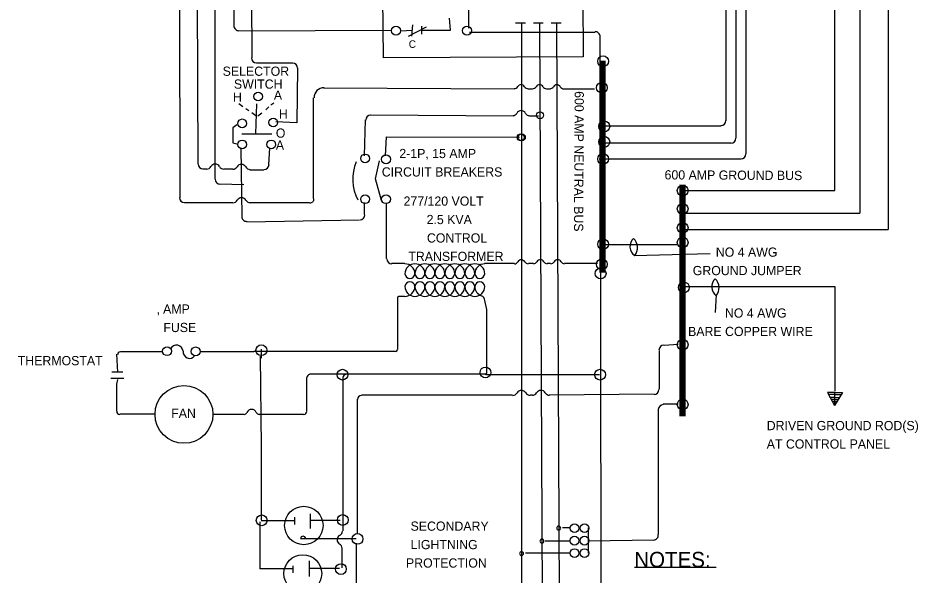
# Model space of a CAD drawing. Extents: x 10006.6 to 10036.5, y 10000 to 10010.3.
# Drawn here: x 10029.2 to 10035.06, y 10003.49 to 10007.12 of the extents above; entities that cross this region are included whole.
import ezdxf

# ---------------------------------------------------------------- set-up
doc = ezdxf.new("R2010")
doc.units = 0
for name, color, linetype in [('DETL-LINE', 7, 'Continuous'), ('DETL-NOTE', 7, 'Continuous'), ('TTLB-TEXT', 7, 'Continuous')]:
    doc.layers.add(name, color=color, linetype=linetype)

# ---------------------------------------------------------------- blocks, each defined once
blk = doc.blocks.new('CIR1')
at = {"layer": 'DETL-LINE'}
blk.add_circle((0, 0), 0.0589, dxfattribs=at)

msp = doc.modelspace()

# ---------------------------------------------------------------- linework, layer by layer
at = {"layer": 'DETL-LINE'}
for p, q in [((10030.357, 10009.214), (10030.37, 10006.172)), ((10030.715, 10009.208), (10030.721, 10006.861)), ((10030.247, 10008.844), (10030.253, 10005.951)), ((10033.809, 10006.452), (10033.809, 10008.766)), ((10033.874, 10006.341), (10033.874, 10008.766)), ((10033.939, 10006.237), (10033.939, 10008.694)), ((10034.517, 10005.9973), (10034.517, 10008.701)), ((10030.481, 10008.642), (10030.481, 10006.075)), ((10030.604, 10008.239), (10030.604, 10007.069)), ((10031.579, 10006.861), (10031.573, 10007.505)), ((10032.873, 10007.505), (10032.879, 10006.868)), ((10032.132, 10007.193), (10032.132, 10007.056)), ((10032.015, 10007.043), (10032.008, 10007.121)), ((10030.637, 10007.037), (10031.631, 10007.043)), ((10031.69, 10007.037), (10031.768, 10007.043)), ((10031.742, 10007.004), (10031.859, 10007.063)), ((10031.768, 10007.076), (10031.761, 10007.004)), ((10031.826, 10007.069), (10031.826, 10007.017)), ((10031.826, 10007.043), (10032.015, 10007.043)), ((10032.437, 10007.089), (10032.502, 10007.089)), ((10032.476, 10007.089), (10032.476, 10003.163)), ((10032.554, 10007.089), (10032.619, 10007.089)), ((10032.593, 10007.089), (10032.613, 10003.163)), ((10032.671, 10007.089), (10032.736, 10007.089)), ((10032.704, 10007.089), (10032.723, 10003.163)), ((10032.138, 10007.03), (10032.957, 10007.03)), ((10032.99, 10006.822), (10032.99, 10006.998)), ((10032.879, 10006.868), (10031.579, 10006.861)), ((10030.754, 10006.829), (10030.988, 10006.829)), ((10032.99, 10005.464), (10032.99, 10006.842)), ((10032.996, 10005.464), (10032.996, 10006.842)), ((10033.003, 10005.464), (10033.003, 10006.842)), ((10033.009, 10005.464), (10033.009, 10006.842)), ((10033.016, 10005.464), (10033.016, 10006.842)), ((10033.022, 10005.464), (10033.022, 10006.842)), ((10031.02, 10006.796), (10031.014, 10006.439)), ((10031.189, 10006.666), (10032.431, 10006.66)), ((10032.522, 10006.66), (10032.548, 10006.66)), ((10032.639, 10006.66), (10032.665, 10006.66)), ((10032.749, 10006.66), (10032.951, 10006.66)), ((10030.845, 10006.556), (10030.864, 10006.569)), ((10031.124, 10005.945), (10031.124, 10006.601)), ((10030.663, 10006.543), (10030.637, 10006.562)), ((10030.702, 10006.517), (10030.682, 10006.53)), ((10030.747, 10006.367), (10030.754, 10006.562)), ((10030.812, 10006.523), (10030.832, 10006.543)), ((10030.747, 10006.484), (10030.721, 10006.504)), ((10030.76, 10006.484), (10030.786, 10006.504)), ((10031.456, 10006.224), (10031.462, 10006.458)), ((10031.495, 10006.491), (10032.424, 10006.484)), ((10032.528, 10006.484), (10032.587, 10006.484)), ((10030.624, 10006.426), (10030.598, 10006.406)), ((10030.598, 10006.406), (10030.598, 10006.309)), ((10031.014, 10006.439), (10030.877, 10006.445)), ((10032.983, 10006.419), (10033.776, 10006.419)), ((10030.656, 10006.367), (10030.851, 10006.367)), ((10031.592, 10006.224), (10031.599, 10006.348)), ((10031.599, 10006.348), (10032.464, 10006.345)), ((10030.598, 10006.309), (10030.624, 10006.302)), ((10030.65, 10006.276), (10030.656, 10005.828)), ((10030.832, 10006.166), (10030.838, 10006.276)), ((10032.983, 10006.309), (10033.841, 10006.309)), ((10031.527, 10006.075), (10031.553, 10006.192)), ((10032.983, 10006.205), (10033.906, 10006.205)), ((10030.403, 10006.14), (10030.429, 10006.14)), ((10030.539, 10006.14), (10030.598, 10006.14)), ((10030.708, 10006.133), (10030.799, 10006.133)), ((10030.513, 10006.042), (10030.669, 10006.036)), ((10031.566, 10005.932), (10031.527, 10006.075)), ((10033.51, 10004.528), (10033.51, 10006.0342)), ((10033.516, 10004.528), (10033.516, 10006.0342)), ((10033.523, 10004.528), (10033.523, 10006.0342)), ((10033.529, 10004.528), (10033.529, 10006.0342)), ((10033.536, 10004.528), (10033.536, 10006.0342)), ((10033.542, 10004.528), (10033.542, 10006.0342)), ((10030.286, 10005.919), (10030.598, 10005.919)), ((10030.708, 10005.919), (10031.098, 10005.919)), ((10031.456, 10005.841), (10031.456, 10005.919)), ((10031.599, 10005.555), (10031.599, 10005.912)), ((10030.689, 10005.795), (10031.423, 10005.808)), ((10033.003, 10005.646), (10033.49, 10005.646)), ((10033.211, 10005.574), (10033.705, 10005.587)), ((10031.716, 10005.522), (10031.631, 10005.522)), ((10032.431, 10005.522), (10032.236, 10005.522)), ((10032.554, 10005.522), (10032.522, 10005.522)), ((10032.665, 10005.522), (10032.645, 10005.522)), ((10032.972, 10005.522), (10032.756, 10005.522)), ((10033.51, 10005.373), (10034.517, 10005.373)), ((10034.517, 10005.373), (10034.517, 10004.69)), ((10031.67, 10005.301), (10031.67, 10004.963)), ((10031.716, 10005.308), (10031.677, 10005.308)), ((10032.236, 10005.282), (10032.249, 10005.223)), ((10033.744, 10005.321), (10033.737, 10005.204)), ((10032.249, 10005.217), (10032.249, 10004.807)), ((10033.497, 10004.996), (10033.406, 10004.989)), ((10029.85, 10004.814), (10029.844, 10004.931)), ((10029.87, 10004.95), (10030.1405, 10004.95)), ((10030.3846, 10004.95), (10030.734, 10004.95)), ((10031.657, 10004.95), (10030.734, 10004.95)), ((10030.784, 10004.907), (10030.784, 10004.965)), ((10033.373, 10004.957), (10033.373, 10004.703)), ((10030.775, 10004.92), (10030.782, 10004.328)), ((10029.883, 10004.814), (10029.811, 10004.814)), ((10029.805, 10004.775), (10029.889, 10004.775)), ((10029.844, 10004.736), (10029.85, 10004.768)), ((10031.079, 10004.56), (10031.079, 10004.781)), ((10031.332, 10004.801), (10031.098, 10004.801)), ((10031.313, 10004.781), (10031.313, 10003.782)), ((10032.242, 10004.801), (10031.332, 10004.801)), ((10029.844, 10004.56), (10029.844, 10004.736)), ((10031.41, 10003.761), (10031.41, 10004.638)), ((10032.34, 10004.664), (10031.436, 10004.664)), ((10032.418, 10004.664), (10032.34, 10004.664)), ((10032.548, 10004.664), (10032.535, 10004.664)), ((10033.341, 10004.671), (10032.658, 10004.664)), ((10034.469, 10004.682), (10034.515, 10004.597)), ((10034.515, 10004.682), (10034.469, 10004.682)), ((10034.515, 10004.669), (10034.476, 10004.669)), ((10034.515, 10004.649), (10034.482, 10004.649)), ((10034.515, 10004.636), (10034.495, 10004.636)), ((10034.515, 10004.682), (10034.567, 10004.682)), ((10034.515, 10004.682), (10034.515, 10004.597)), ((10034.567, 10004.682), (10034.515, 10004.597)), ((10034.515, 10004.682), (10034.515, 10004.597)), ((10034.515, 10004.669), (10034.56, 10004.669)), ((10034.515, 10004.649), (10034.547, 10004.649)), ((10034.515, 10004.636), (10034.541, 10004.636)), ((10033.497, 10004.606), (10033.399, 10004.606)), ((10034.515, 10004.623), (10034.502, 10004.623)), ((10034.515, 10004.61), (10034.508, 10004.61)), ((10034.515, 10004.623), (10034.534, 10004.623)), ((10034.515, 10004.61), (10034.521, 10004.61)), ((10030.091, 10004.541), (10029.863, 10004.541)), ((10030.468, 10004.541), (10030.669, 10004.541)), ((10030.767, 10004.541), (10031.059, 10004.541)), ((10033.367, 10004.573), (10033.367, 10003.7575)), ((10030.782, 10004.339), (10030.782, 10003.852)), ((10030.773, 10003.841), (10030.773, 10003.533)), ((10032.795, 10003.8), (10032.743, 10003.8)), ((10032.912, 10003.637), (10032.912, 10003.8)), ((10031.404, 10003.4196), (10031.404, 10003.702)), ((10032.795, 10003.715), (10032.632, 10003.715)), ((10033.3373, 10003.7215), (10032.912, 10003.715)), ((10031.309, 10003.54), (10031.309, 10003.67)), ((10032.795, 10003.637), (10032.502, 10003.637)), ((10031.095, 10003.586), (10031.095, 10003.484)), ((10030.9481, 10003.533), (10030.773, 10003.533)), ((10030.989, 10003.554), (10030.989, 10003.507))]:
    msp.add_line(p, q, dxfattribs=at)
for centre, radius in [((10033.0078, 10006.8396), 0.0351), ((10032.9998, 10006.6676), 0.0351), ((10032.5979, 10006.4878), 0.0228), ((10032.5979, 10006.4878), 0.0228), ((10033.0158, 10006.4156), 0.0351), ((10032.4718, 10006.3441), 0.0228), ((10032.4789, 10006.3441), 0.0228), ((10033.0158, 10006.3146), 0.0351), ((10033.0078, 10006.2036), 0.0351), ((10033.5258, 10005.9973), 0.0351), ((10033.5258, 10005.8785), 0.0351), ((10033.5258, 10005.7548), 0.0351), ((10033.5258, 10005.6596), 0.0351), ((10033.0078, 10005.6486), 0.0351), ((10032.9998, 10005.5176), 0.0351), ((10032.9918, 10005.4576), 0.0351), ((10033.5338, 10005.3666), 0.0351), ((10030.7838, 10004.9576), 0.0351), ((10033.5258, 10004.9936), 0.0351), ((10031.3118, 10004.7986), 0.0351), ((10032.2422, 10004.8128), 0.0351), ((10032.9882, 10004.7986), 0.0351), ((10030.2801, 10004.54), 0.1884), ((10033.5258, 10004.6046), 0.0351), ((10031.0602, 10003.8161), 0.1249), ((10030.7858, 10003.8496), 0.0351), ((10031.3134, 10003.852), 0.0351), ((10032.822, 10003.7988), 0.0287), ((10032.887, 10003.7988), 0.0287), ((10031.4098, 10003.7286), 0.0351), ((10032.822, 10003.7175), 0.0287), ((10032.887, 10003.7175), 0.0287), ((10032.822, 10003.6363), 0.0287), ((10032.887, 10003.6363), 0.0287), ((10031.0533, 10003.5029), 0.123), ((10031.3015, 10003.5324), 0.0351)]:
    msp.add_circle(centre, radius, dxfattribs=at)
for centre, radius, start, end in [((10030.6375, 10007.0711), 0.0325, 180.13954, 270.41156), ((10032.9561, 10007.0003), 0.0325, 0, 90.11455), ((10030.7521, 10006.8612), 0.0325, 180.17293, 269.77653), ((10030.9862, 10006.7952), 0.0325, 359.77653, 89.77653), ((10032.4746, 10006.6613), 0.026, 29.73672, 149.73672), ((10032.5943, 10006.6608), 0.026, 29.73672, 149.73672), ((10032.7069, 10006.6603), 0.026, 29.73672, 149.73672), ((10031.1914, 10006.6022), 0.065, 89.73672, 179.9816), ((10032.4297, 10006.6875), 0.026, 269.73672, 329.73672), ((10032.5197, 10006.6871), 0.026, 209.73672, 269.73672), ((10032.5494, 10006.687), 0.026, 269.73672, 329.73672), ((10032.6395, 10006.6866), 0.026, 209.73672, 269.73672), ((10032.662, 10006.6865), 0.026, 269.73672, 329.73672), ((10032.7521, 10006.6861), 0.026, 209.73672, 269.73672), ((10032.4748, 10006.4859), 0.0325, 26.229, 153.4534), ((10031.4956, 10006.4561), 0.0325, 89.8412, 178.95021), ((10032.4224, 10006.512), 0.026, 269.8412, 333.4534), ((10032.5272, 10006.5117), 0.026, 206.229, 269.8412), ((10033.7749, 10006.4538), 0.0325, 270, 0), ((10033.8399, 10006.338), 0.0325, 270, 0), ((10033.9049, 10006.236), 0.0325, 270, 0), ((10030.4043, 10006.1706), 0.0325, 180.26152, 269.47418), ((10030.4832, 10006.1374), 0.0325, 29.47418, 149.47418), ((10030.6535, 10006.1358), 0.0325, 29.47418, 149.47418), ((10030.8014, 10006.167), 0.0325, 269.47418, 358.76596), ((10031.6782, 10006.0719), 0.2998, 157.90019, 206.91103), ((10030.4272, 10006.1704), 0.0325, 269.47418, 329.47418), ((10030.5398, 10006.1694), 0.0325, 209.47418, 269.47418), ((10030.5975, 10006.1688), 0.0325, 269.47418, 329.47418), ((10030.7101, 10006.1678), 0.0325, 209.47418, 269.47418), ((10030.5158, 10006.0721), 0.0325, 180.08382, 269.38139), ((10030.2834, 10005.9516), 0.0325, 180.02499, 269.85957), ((10030.5989, 10005.9508), 0.0325, 269.85957, 329.85957), ((10030.6551, 10005.9182), 0.0325, 29.85957, 149.85957), ((10030.7114, 10005.9506), 0.0325, 209.85957, 269.85957), ((10031.1002, 10005.9431), 0.026, 269.85957, 359.9816), ((10030.6882, 10005.8292), 0.0325, 180.41583, 270.8332), ((10031.4254, 10005.8399), 0.0325, 270.8332, 359.77648), ((10033.2552, 10005.6334), 0.0725, 133.00439, 235.41993), ((10033.1488, 10005.6255), 0.0833, 321.54514, 46.87918), ((10031.6335, 10005.5526), 0.0325, 180.12584, 270), ((10031.7831, 10005.4551), 0.065, 90, 180), ((10031.7181, 10005.4551), 0.065, 0, 90), ((10031.7831, 10005.4551), 0.065, 0, 90), ((10031.8481, 10005.4551), 0.065, 90, 180), ((10031.8481, 10005.4551), 0.065, 0, 90), ((10031.9131, 10005.4551), 0.065, 90, 180), ((10031.9131, 10005.4551), 0.065, 0, 90), ((10031.9781, 10005.4551), 0.065, 90, 180), ((10031.9781, 10005.4551), 0.065, 0, 90), ((10032.0431, 10005.4551), 0.065, 90, 180), ((10032.0431, 10005.4551), 0.065, 0, 90), ((10032.1081, 10005.4551), 0.065, 90, 180), ((10032.1081, 10005.4551), 0.065, 0, 90), ((10032.1731, 10005.4551), 0.065, 90, 180), ((10032.1731, 10005.4551), 0.065, 0, 90), ((10032.2381, 10005.4551), 0.065, 90, 180), ((10032.4307, 10005.5464), 0.026, 270.0947, 330.0947), ((10032.4758, 10005.5205), 0.026, 30.0947, 150.0947), ((10032.5208, 10005.5466), 0.026, 210.0947, 270.0947), ((10032.5548, 10005.5466), 0.026, 270.0947, 330.0947), ((10032.5999, 10005.5207), 0.026, 30.0947, 150.0947), ((10032.6449, 10005.5468), 0.026, 210.0947, 270.0947), ((10032.6674, 10005.5468), 0.026, 270.0947, 330.0947), ((10032.7124, 10005.5209), 0.026, 30.0947, 150.0947), ((10032.7574, 10005.547), 0.026, 210.0947, 270.0947), ((10031.7506, 10005.458), 0.0326, 185.09993, 354.90007), ((10031.8156, 10005.458), 0.0326, 185.09993, 354.90007), ((10031.8806, 10005.458), 0.0326, 185.09993, 354.90007), ((10031.9456, 10005.458), 0.0326, 185.09993, 354.90007), ((10032.0106, 10005.458), 0.0326, 185.09993, 354.90007), ((10032.0756, 10005.458), 0.0326, 185.09993, 354.90007), ((10032.1406, 10005.458), 0.0326, 185.09993, 354.90007), ((10032.2056, 10005.458), 0.0326, 185.09993, 354.90007), ((10031.7506, 10005.3705), 0.0326, 5.09993, 174.90007), ((10031.8156, 10005.3705), 0.0326, 5.09993, 174.90007), ((10031.8806, 10005.3705), 0.0326, 5.09993, 174.90007), ((10031.9456, 10005.3705), 0.0326, 5.09993, 174.90007), ((10032.0106, 10005.3705), 0.0326, 5.09993, 174.90007), ((10032.0756, 10005.3705), 0.0326, 5.09993, 174.90007), ((10032.1406, 10005.3705), 0.0326, 5.09993, 174.90007), ((10032.2056, 10005.3705), 0.0326, 5.09993, 174.90007), ((10033.7888, 10005.371), 0.0741, 134.81084, 232.42017), ((10033.6829, 10005.3643), 0.08, 319.36794, 47.86307), ((10031.7181, 10005.3734), 0.065, 270, 0), ((10031.7831, 10005.3734), 0.065, 180, 270), ((10031.8481, 10005.3734), 0.065, 180, 270), ((10031.7831, 10005.3734), 0.065, 270, 0), ((10031.9131, 10005.3734), 0.065, 180, 270), ((10031.8481, 10005.3734), 0.065, 270, 0), ((10031.9781, 10005.3734), 0.065, 180, 270), ((10031.9131, 10005.3734), 0.065, 270, 0), ((10032.0431, 10005.3734), 0.065, 180, 270), ((10031.9781, 10005.3734), 0.065, 270, 0), ((10032.1081, 10005.3734), 0.065, 180, 270), ((10032.0431, 10005.3734), 0.065, 270, 0), ((10032.1731, 10005.3734), 0.065, 180, 270), ((10032.1081, 10005.3734), 0.065, 270, 0), ((10032.2381, 10005.3734), 0.065, 180, 250.04485), ((10032.1731, 10005.3734), 0.065, 270, 0), ((10031.679, 10005.2987), 0.00975, 90, 180), ((10032.2048, 10005.2818), 0.0325, 358.36206, 70.04485), ((10032.231, 10005.218), 0.0195, 0, 12.2171), ((10030.2317, 10004.9474), 0.0434, 4.58337, 154.04987), ((10033.4041, 10004.9585), 0.0325, 91.49484, 180.00294), ((10029.8667, 10004.928), 0.0195, 90.18522, 181.41306), ((10030.316, 10004.9464), 0.0416, 173.80012, 324.96254), ((10031.6595, 10004.9601), 0.00975, 270, 0), ((10032.2407, 10004.8084), 0.00975, 270, 0), ((10031.0992, 10004.7791), 0.0195, 90, 180), ((10031.3342, 10004.7791), 0.0195, 90, 179.72277), ((10032.4761, 10004.6639), 0.0325, 30.01658, 150.71864), ((10032.6036, 10004.6639), 0.0325, 30.8501, 149.88512), ((10033.3391, 10004.7016), 0.0325, 270.36761, 0.00294), ((10031.4347, 10004.6367), 0.026, 90, 180), ((10032.4194, 10004.6957), 0.0325, 270.36761, 330.71864), ((10032.5324, 10004.6965), 0.0325, 210.01658, 270.36761), ((10032.5474, 10004.6966), 0.0325, 270.36761, 329.88512), ((10032.6594, 10004.6973), 0.0325, 210.8501, 270.36761), ((10033.3997, 10004.571), 0.0325, 90, 180), ((10029.8621, 10004.5595), 0.0195, 178.48287, 270), ((10030.6722, 10004.5595), 0.0195, 270, 337.97569), ((10030.7204, 10004.54), 0.0325, 22.02431, 157.97569), ((10030.7686, 10004.5595), 0.0195, 202.02431, 270), ((10031.0602, 10004.5595), 0.0195, 270, 0), ((10032.7193, 10003.799), 0.013, 0, 180), ((10031.2787, 10003.7801), 0.0325, 299.59446, 0), ((10032.7193, 10003.799), 0.013, 180, 0), ((10033.3347, 10003.7539), 0.0325, 274.52389, 6.3158), ((10031.0549, 10003.729), 0.0169, 5.3234, 175.10921), ((10031.3091, 10003.7235), 0.0325, 119.59446, 240.40554), ((10031.277, 10003.667), 0.0325, 0, 60.40554), ((10032.6103, 10003.7143), 0.013, 0, 180), ((10032.6103, 10003.7143), 0.013, 180, 0), ((10032.4771, 10003.6335), 0.013, 0, 180), ((10032.4771, 10003.6335), 0.013, 180, 0)]:
    msp.add_arc(centre, radius, start, end, dxfattribs=at)
at = {"layer": 'DETL-NOTE'}
msp.add_line((10033.2119, 10003.5453), (10033.745, 10003.5453), dxfattribs=at)
at = {"layer": 'TTLB-TEXT'}
for p, q in [((10034.6795, 10009.253), (10034.6795, 10005.8506)), ((10034.864, 10008.662), (10034.864, 10005.7436)), ((10032.99, 10006.809), (10032.996, 10002.008)), ((10033.5258, 10005.9973), (10034.517, 10005.9973)), ((10033.5004, 10005.8506), (10034.6795, 10005.8506)), ((10033.5258, 10005.7436), (10034.864, 10005.7436)), ((10032.9914, 10005.4235), (10032.9914, 10004.8315)), ((10032.2491, 10004.7996), (10032.9856, 10004.7996)), ((10030.9985, 10003.871), (10030.9985, 10003.8222)), ((10031.1012, 10003.8914), (10031.1012, 10003.7958)), ((10030.9604, 10003.8468), (10030.782, 10003.8468)), ((10030.999, 10003.847), (10030.96, 10003.847)), ((10031.099, 10003.8502), (10031.2973, 10003.8502)), ((10031.4007, 10003.7299), (10031.0379, 10003.7299)), ((10030.9888, 10003.5329), (10030.9498, 10003.5329)), ((10031.0956, 10003.5383), (10031.2922, 10003.5383))]:
    msp.add_line(p, q, dxfattribs=at)

# ---------------------------------------------------------------- block references
at = {"layer": 'DETL-LINE', "xscale": 0.4875000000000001, "yscale": 0.4875000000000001}
for p in [(10031.66, 10007.039), (10032.122, 10007.039), (10030.763, 10006.61), (10030.659, 10006.435), (10030.861, 10006.441), (10030.659, 10006.298), (10030.848, 10006.298), (10031.459, 10006.207), (10031.595, 10006.201), (10031.459, 10005.941), (10031.595, 10005.941), (10030.17, 10004.951), (10030.356, 10004.95)]:
    msp.add_blockref('CIR1', p, dxfattribs=at)

# ---------------------------------------------------------------- texts
at = {"layer": 'DETL-NOTE'}
for s, height, p in [('C', 0.049, (10031.743, 10006.927)), ('SELECTOR', 0.06, (10030.532, 10006.745)), ('SWITCH', 0.06, (10030.605, 10006.661)), ('H', 0.06, (10030.599, 10006.576)), ('A', 0.06, (10030.865, 10006.589)), ('H', 0.06, (10030.898, 10006.466)), ('O ', 0.06, (10030.878, 10006.342)), ('A', 0.06, (10030.878, 10006.264)), ('2-1P, 15 AMP', 0.06, (10031.6816, 10006.209)), ('CIRCUIT BREAKERS', 0.06, (10031.5676, 10006.089)), ('277/120 VOLT', 0.06, (10031.7093, 10005.899)), ('2.5 KVA', 0.06, (10031.8593, 10005.779)), ('CONTROL', 0.06, (10031.8614, 10005.659)), ('TRANSFORMER', 0.06, (10031.7403, 10005.539)), ('NO 4 AWG', 0.06, (10033.7416, 10005.5666)), ('GROUND JUMPER', 0.06, (10033.5916, 10005.4466)), ('‚ AMP', 0.06, (10030.104, 10005.196)), ('NO 4 AWG', 0.06, (10033.801, 10005.17)), ('FUSE', 0.06, (10030.146, 10005.076)), ('BARE COPPER WIRE', 0.06, (10033.561, 10005.05)), ('THERMOSTAT', 0.06, (10029.198, 10004.86)), ('FAN', 0.06, (10030.197, 10004.517)), ('DRIVEN GROUND ROD(S)', 0.06, (10034.073, 10004.437)), ('AT CONTROL PANEL', 0.06, (10034.073, 10004.317)), ('SECONDARY', 0.06, (10031.755, 10003.782)), ('LIGHTNING', 0.06, (10031.755, 10003.662)), ('NOTES:', 0.1, (10033.2105, 10003.5444)), ('PROTECTION', 0.06, (10031.725, 10003.542))]:
    msp.add_text(s, height=height, dxfattribs=at).set_placement(p)
for s, rotation, p in [('600 AMP NEUTRAL BUS', 269.71501, (10032.823, 10006.645)), ('600 AMP GROUND BUS', 359.71501, (10033.408, 10006.0702))]:
    msp.add_text(s, height=0.06, rotation=rotation, dxfattribs=at).set_placement(p)

doc.saveas('drawing.dxf')
